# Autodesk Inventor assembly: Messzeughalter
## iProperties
Created: 2007-12
Part Number: Messzeughalter
Document SubType Name: Assembly
Designer: Benno
Manufacturer: Standard
Standards Organization: Custom
Author: Benno
